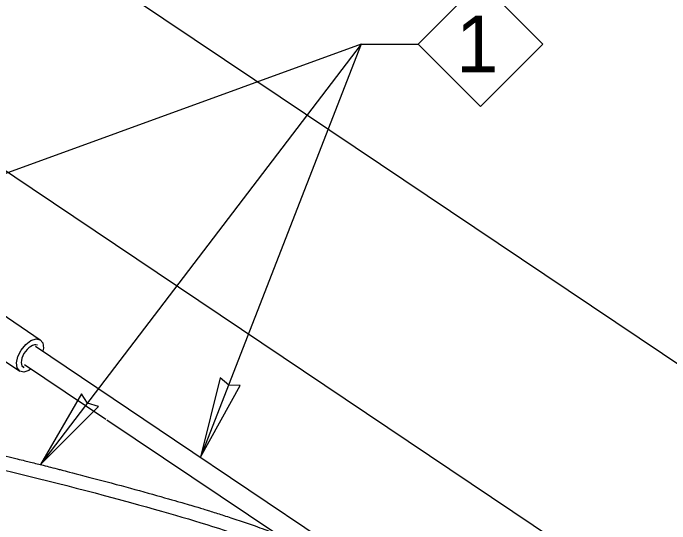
# Model space of a CAD drawing. Extents: x 99862 to 103151, y 100000 to 105076.
# Drawn here: x 100639 to 100823.8, y 100464 to 100607.6 of the extents above; entities that cross this region are included whole.
import ezdxf

# ---------------------------------------------------------------- set-up
doc = ezdxf.new("R2010")
doc.units = 0
for name, color, linetype in [('Level 1', 7, 'Continuous'), ('Level 11', 7, 'Continuous'), ('Level 15', 7, 'Continuous'), ('Level 20', 7, 'Continuous')]:
    doc.layers.add(name, color=color, linetype=linetype)

msp = doc.modelspace()

# ---------------------------------------------------------------- linework, layer by layer
at = {"layer": 'Level 1'}
for p, q in [((100681.41, 100605.98), (100651.82, 100625.85)), ((100707.03, 100588.78), (100681.41, 100605.98)), ((100742.36, 100565.06), (100707.03, 100588.78)), ((100644.29, 100558.24), (100615.59, 100577.51)), ((100849.22, 100493.32), (100742.36, 100565.06)), ((100800.85, 100453.13), (100644.29, 100558.24)), ((100645.23, 100513.93), (100684.37, 100487.66)), ((100642.2, 100508.79), (100665.06, 100493.44)), ((100665.34, 100493.25), (100713.15, 100461.15)), ((100684.37, 100487.66), (100744.61, 100447.22))]:
    msp.add_line(p, q, dxfattribs=at)
for points in [[(100633.72, 100524.43), (100632.55, 100524.67), (100631.12, 100524.2), (100629.65, 100523.09), (100628.36, 100521.51), (100627.44, 100519.7), (100627.05, 100517.94), (100627.23, 100516.49), (100627.96, 100515.58), (100640.83, 100506.93), (100640.1, 100507.85), (100639.92, 100509.29), (100640.32, 100511.05), (100641.23, 100512.86), (100642.53, 100514.44), (100644, 100515.55), (100645.43, 100516.03), (100646.6, 100515.79)], [(100633.72, 100524.43), (100646.6, 100515.79), (100647.33, 100514.88), (100647.51, 100513.43), (100647.33, 100512.65)], [(100645.82, 100514.27), (100645.82, 100514.27), (100645.35, 100514.31), (100644.95, 100514.34), (100644.4, 100514.11), (100643.92, 100513.92), (100643.37, 100513.46), (100642.9, 100513.06), (100642.44, 100512.44), (100642.03, 100511.9), (100641.72, 100511.22), (100641.45, 100510.62), (100641.35, 100509.97), (100641.25, 100509.41), (100641.36, 100508.9), (100641.45, 100508.46), (100641.77, 100508.16), (100642.03, 100507.9), (100642.03, 100507.9)], [(100643.9, 100507.53), (100643.43, 100507.17), (100642, 100506.7), (100640.83, 100506.93)]]:
    msp.add_lwpolyline(points, dxfattribs=at)
at = {"layer": 'Level 11'}
for points in [[(100506.81, 100538.75), (100509.28, 100537.16), (100511.48, 100535.62), (100515.39, 100532.62), (100517.08, 100531.16), (100519.24, 100528.98), (100519.9, 100528.25), (100520.64, 100527.34), (100520.78, 100527.16), (100521.06, 100526.79), (100521.2, 100526.6), (100521.62, 100526.02), (100521.88, 100525.63), (100523.14, 100523.57), (100523.96, 100521.74), (100525.28, 100517.73), (100525.79, 100515.55), (100526.25, 100512.59), (100526.35, 100511.84), (100526.44, 100511.07), (100526.47, 100510.84), (100526.48, 100510.76), (100526.5, 100510.62), (100526.54, 100510.27), (100526.7, 100508.81), (100526.87, 100507.51), (100527.29, 100504.59), (100527.59, 100502.89), (100528.05, 100500.75), (100528.21, 100500.1), (100528.45, 100499.23), (100528.52, 100498.96), (100528.64, 100498.58), (100528.7, 100498.4), (100528.76, 100498.22), (100528.79, 100498.11), (100528.81, 100498.05), (100529.12, 100497.18), (100529.49, 100496.39), (100530.43, 100494.85), (100530.99, 100494.1), (100531.99, 100492.99), (100532.35, 100492.62), (100532.93, 100492.08), (100533.14, 100491.9), (100533.54, 100491.55), (100533.75, 100491.38), (100534.77, 100490.58), (100535.61, 100490.03), (100537.34, 100489.13), (100538.23, 100488.77), (100539.39, 100488.42), (100539.68, 100488.34), (100539.98, 100488.27), (100540.1, 100488.24), (100540.15, 100488.23), (100540.31, 100488.19), (100540.43, 100488.17), (100541.02, 100488.06), (100541.57, 100487.99), (100543.42, 100487.84), (100544.94, 100487.85), (100547.59, 100488.03), (100548.54, 100488.12), (100550.05, 100488.3), (100550.83, 100488.4), (100551.77, 100488.54), (100552.25, 100488.62), (100552.5, 100488.65), (100552.6, 100488.67), (100552.67, 100488.68), (100552.7, 100488.69), (100555.22, 100489.09), (100558.08, 100489.41), (100564.61, 100489.91), (100568.28, 100490.08), (100574.4, 100490.25), (100576.54, 100490.29), (100579.35, 100490.31), (100579.91, 100490.32), (100581.06, 100490.32), (100581.65, 100490.32), (100583.39, 100490.32), (100589.15, 100490.28), (100594.71, 100490.02), (100603.32, 100489.33), (100607.5, 100488.85), (100612.55, 100488.07), (100613.55, 100487.91), (100615.54, 100487.56), (100616.52, 100487.38), (100619.55, 100486.82), (100621.66, 100486.4), (100628.31, 100485.02), (100633.13, 100483.93), (100640.95, 100482.07), (100643.66, 100481.41), (100647.87, 100480.35), (100649.29, 100479.99), (100652.2, 100479.25), (100653.68, 100478.86), (100667.16, 100475.34), (100676.98, 100472.68), (100686.57, 100469.93), (100688.36, 100469.41), (100690.83, 100468.67), (100691.62, 100468.43), (100693.16, 100467.96), (100696.97, 100466.78), (100700.51, 100465.63), (100705.84, 100463.83), (100708.35, 100462.94), (100711.26, 100461.85), (100711.84, 100461.63), (100712.68, 100461.31), (100712.96, 100461.2), (100713.53, 100460.98), (100713.82, 100460.86), (100715.28, 100460.27), (100716.51, 100459.76), (100722.97, 100456.94), (100729.1, 100453.94), (100743.02, 100445.79)], [(100504.9, 100535.46), (100514.41, 100529.33), (100521.66, 100519.65), (100523.74, 100501.03), (100526.75, 100492.46), (100534.5, 100485.64), (100543.98, 100483.44), (100562.71, 100486.45), (100599.45, 100486.6), (100630.28, 100481.04), (100678.15, 100468.55), (100702.87, 100461.04), (100720.3, 100454.27), (100741.26, 100442.31)]]:
    msp.add_open_spline(points, degree=3, dxfattribs=at)
at = {"layer": 'Level 15'}
for q in [(100612.81, 100553.78), (100646.72, 100480.64), (100691.73, 100482.71), (100752.94, 100598.95)]:
    msp.add_line((100736.94, 100598.95), q, dxfattribs=at)
for points in [[(100691.73, 100482.71), (100702.82, 100502.89), (100699.65, 100503), (100697.26, 100505.07)], [(100646.72, 100480.64), (100662.96, 100496.96), (100659.95, 100497.93), (100658.22, 100500.59)]]:
    msp.add_lwpolyline(points, close=True, dxfattribs=at)
at = {"layer": 'Level 20'}
msp.add_lwpolyline([(100770.5, 100616.51), (100788.05, 100598.95), (100770.5, 100581.4), (100752.94, 100598.95)], close=True, dxfattribs=at)

# ---------------------------------------------------------------- texts
msp.add_text('1', height=16, dxfattribs=at).set_placement((100763.63, 100590.95))

doc.saveas('drawing.dxf')
